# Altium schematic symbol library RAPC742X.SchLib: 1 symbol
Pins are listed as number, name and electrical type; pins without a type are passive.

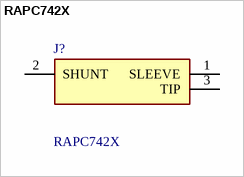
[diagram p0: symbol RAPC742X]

## RAPC742X
designator J?
Jack, Power; PC Mount; 1 mm; 50 Milliohms (Max.); 250 VAC for 1 Minute; 3 A; Manufacturer_Name: Switchcraft; Geometry.Height: 7.62mm
footprint RAPC742X
pins: 1 SLEEVE, 2 SHUNT, 3 TIP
